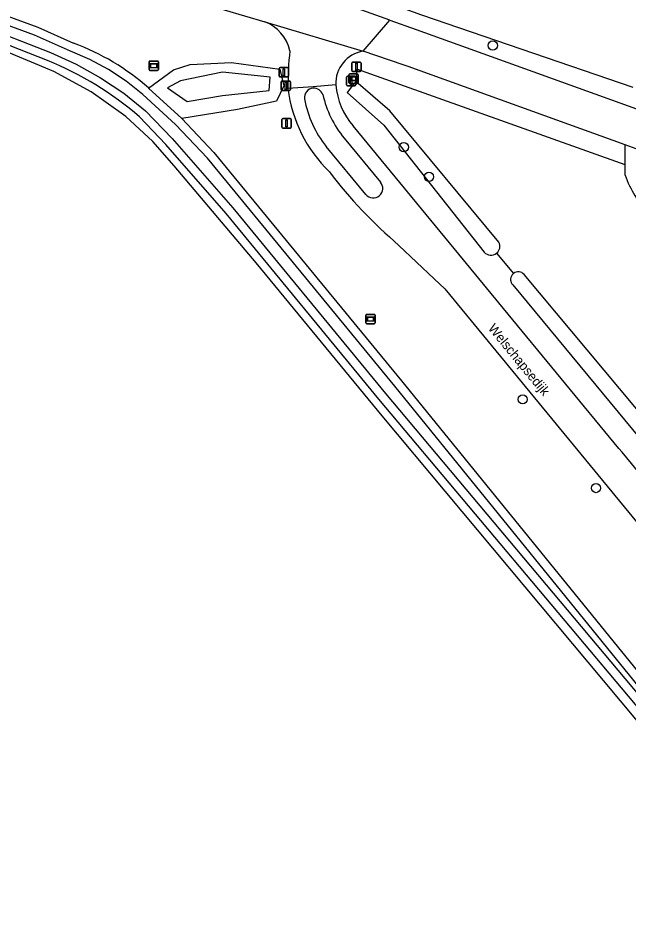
# Model space of a CAD drawing. Extents: x 156061 to 157804, y 383451 to 385640.
# Drawn here: x 156564.9 to 156629.3, y 384979.6 to 385074 of the extents above; entities that cross this region are included whole.
import ezdxf

# ---------------------------------------------------------------- set-up
doc = ezdxf.new("R2010")
doc.units = 0
for name, color, linetype in [('IMGEO_Afsluitpaal', 7, 'Continuous'), ('IMGEO_Berm_groen', 7, 'Continuous'), ('IMGEO_Boom', 7, 'Continuous'), ('IMGEO_Fietspad_gesloten', 7, 'Continuous'), ('IMGEO_Fietspad_open', 7, 'Continuous'), ('IMGEO_Groenvoorziening', 7, 'Continuous'), ('IMGEO_Loofbos', 7, 'Continuous'), ('IMGEO_Openbare_ruimte_label', 7, 'Continuous'), ('IMGEO_Rijbaan_lokaal_gesloten', 7, 'Continuous'), ('IMGEO_Rijbaan_lokaal_open', 7, 'Continuous'), ('IMGEO_Verkeersbordpaal', 7, 'Continuous'), ('IMGEO_Verklikker', 7, 'Continuous'), ('IMGEO_Waterloop', 7, 'Continuous')]:
    doc.layers.add(name, color=color, linetype=linetype)

msp = doc.modelspace()

# ---------------------------------------------------------------- linework, layer by layer
at = {"layer": 'IMGEO_Afsluitpaal'}
for p, q in [((156592.644, 385066.48), (156592.644, 385067.28)), ((156592.644, 385067.28), (156592.644, 385066.48)), ((156592.744, 385067.38), (156593.534, 385067.38)), ((156593.534, 385067.38), (156592.744, 385067.38)), ((156593.634, 385067.28), (156593.634, 385066.48)), ((156593.634, 385066.48), (156593.634, 385067.28)), ((156593.534, 385066.38), (156592.744, 385066.38)), ((156592.744, 385066.38), (156593.534, 385066.38))]:
    msp.add_line(p, q, dxfattribs=at)
msp.add_lwpolyline([(156593.064, 385067.255), (156593.214, 385067.255), (156593.214, 385066.505), (156593.064, 385066.505), (156593.064, 385067.255)], dxfattribs=at)
for centre, start, end in [((156592.744, 385067.28), 90, 180), ((156592.744, 385067.28), 90, 180), ((156593.534, 385067.28), 0, 90), ((156593.534, 385067.28), 360, 90), ((156592.744, 385066.48), 180, 270), ((156592.744, 385066.48), 180, 270), ((156593.534, 385066.48), 270, 0), ((156593.534, 385066.48), 270, 0)]:
    msp.add_arc(centre, 0.1, start, end, dxfattribs=at)
at = {"layer": 'IMGEO_Berm_groen'}
for points in [[(156628.988, 385058.529), (156600.645, 385068.645), (156600.53, 385067.343)], [(156628.988, 385058.529), (156628.997, 385060.649)], [(156615.412, 385049.211), (156617.202, 385047.075)]]:
    msp.add_lwpolyline(points, dxfattribs=at)
at = {"layer": 'IMGEO_Boom'}
for centre in [(156615.004, 385071.134), (156605.602, 385060.399), (156608.268, 385057.279), (156618.158, 385033.777), (156625.908, 385024.415)]:
    msp.add_circle(centre, 0.489, dxfattribs=at)
at = {"layer": 'IMGEO_Fietspad_gesloten'}
for points in [[(156598.43, 385066.983), (156596.028, 385066.78), (156593.377, 385066.578)], [(156952.011, 384636.1), (156951.649, 384636.454), (156945.248, 384644.122), (156913.262, 384682.917), (156857.952, 384750), (156766.231, 384861.244), (156717.241, 384920.698), (156651.898, 385000), (156634.534, 385021.048), (156628.661, 385028.193), (156628.314, 385028.596), (156616.132, 385043.374), (156611.412, 385049.1), (156600.259, 385062.638)], [(156601.608, 385055.389), (156597.416, 385060.46)], [(156599.308, 385061.359), (156603.145, 385056.713)], [(156605.091, 385050.034), (156608.817, 385046.509), (156609.374, 385045.976), (156609.93, 385045.436), (156647.34, 385000), (156714.453, 384918.502), (156763.606, 384858.813), (156853.32, 384750), (156910.525, 384680.616)]]:
    msp.add_lwpolyline(points, dxfattribs=at)
for centre, radius, start, end in [((156607.945, 385068.367), 14.677, 186.9996, 226.02597), ((156596.118, 385065.621), 1.007, 94.46915, 187.32789), ((156596.092, 385065.59), 1.037, 20.93037, 92.86408), ((156606.147, 385067.674), 7.748, 185.11591, 220.54078), ((156606.423, 385067.609), 11.499, 190.60349, 218.44042), ((156607.812, 385068.363), 11.017, 192.60084, 219.47845), ((156637.682, 385088.158), 50.156, 217.24271, 229.47375), ((156602.372, 385056.056), 1.014, 221.10182, 40.38261)]:
    msp.add_arc(centre, radius, start, end, dxfattribs=at)
at = {"layer": 'IMGEO_Fietspad_open'}
for centre, radius, start, end in [((156589.468, 385069.69), 4.199, 12.27269, 69.6849), ((156628.596, 385066.878), 35.221, 173.96373, 180.48847), ((156601.862, 385067.137), 3.436, 99.13504, 182.56298)]:
    msp.add_arc(centre, radius, start, end, dxfattribs=at)
at = {"layer": 'IMGEO_Groenvoorziening'}
for points in [[(156435.058, 385119.831), (156500, 385096.915), (156553.673, 385077.975), (156566.959, 385073.059), (156570.736, 385071.384)], [(156567.978, 385069.561), (156552.813, 385075.489), (156500, 385094.073), (156435.738, 385116.684), (156396.115, 385073.309)], [(156704.185, 384910.355), (156680.539, 384938.812), (156675.709, 384944.624), (156664.3, 384958.479), (156630.109, 385000), (156603.329, 385032.022), (156590.034, 385048.185), (156581.376, 385058.421), (156579.11, 385060.987), (156576.247, 385063.649), (156574.166, 385065.132), (156572.592, 385066.255), (156568.65, 385068.402), (156563.107, 385070.714), (156551.893, 385074.785), (156500, 385093.06), (156436.131, 385115.542), (156397.25, 385072.572), (156397.423, 385071.829)], [(156566.301, 385089.228), (156607.493, 385074.38), (156629.792, 385066.728)], [(156578.657, 385066.646), (156581.272, 385068.56), (156583.033, 385069.112), (156587.408, 385069.329), (156592.511, 385068.62), (156592.952, 385066.882), (156592.158, 385065.258), (156588.056, 385064.392), (156582.153, 385063.43)], [(156582.153, 385063.43), (156578.657, 385066.646)], [(156673.482, 384950.407), (156672.799, 384949.599), (156658.27, 384967.539), (156631.387, 385000), (156602.972, 385033.813), (156586.855, 385053.4), (156580.462, 385060.696), (156577.709, 385063.589)], [(156582.153, 385063.43), (156585.552, 385059.831), (156605.373, 385035.73), (156634.41, 385000), (156674.271, 384951.339), (156673.482, 384950.407)]]:
    msp.add_lwpolyline(points, dxfattribs=at)
for centre, radius, start, end in [((156561.982, 385047.759), 25.195, 48.55963, 69.66829), ((156554.665, 385036.954), 35.22, 49.13426, 67.79013)]:
    msp.add_arc(centre, radius, start, end, dxfattribs=at)
at = {"layer": 'IMGEO_Loofbos'}
msp.add_lwpolyline([(156628.983, 385057.433), (156628.988, 385058.529)], dxfattribs=at)
msp.add_arc((156640.277, 385061.528), 12.014, 199.92856, 222.69113, dxfattribs=at)
at = {"layer": 'IMGEO_Rijbaan_lokaal_gesloten'}
for points in [[(156324.12, 385168.823), (156326.224, 385167.859), (156431.778, 385130.12), (156500, 385105.742), (156557.53, 385085.067), (156567.974, 385081.116), (156578.058, 385077.449), (156590.926, 385073.627)], [(156604.139, 385073.809), (156569.753, 385086.114)], [(156601.317, 385070.529), (156604.139, 385073.809)], [(156590.926, 385073.627), (156601.317, 385070.529)]]:
    msp.add_lwpolyline(points, dxfattribs=at)
at = {"layer": 'IMGEO_Rijbaan_lokaal_open'}
for points in [[(156604.139, 385073.809), (156606.916, 385072.811), (156634.591, 385062.861), (156662.26, 385052.848), (156695.623, 385040.804)], [(156628.997, 385060.649), (156606.086, 385068.91), (156605.548, 385069.093), (156601.317, 385070.529)], [(156632.086, 385059.534), (156628.997, 385060.649)]]:
    msp.add_lwpolyline(points, dxfattribs=at)
at = {"layer": 'IMGEO_Verkeersbordpaal'}
for p, q in [((156600.108, 385068.48), (156600.108, 385069.28)), ((156600.108, 385069.28), (156600.108, 385068.48)), ((156600.208, 385069.38), (156600.998, 385069.38)), ((156600.998, 385069.38), (156600.208, 385069.38)), ((156601.098, 385069.28), (156601.098, 385068.48)), ((156601.098, 385068.48), (156601.098, 385069.28)), ((156592.443, 385067.912), (156592.443, 385068.712)), ((156592.443, 385068.712), (156592.443, 385067.912)), ((156592.543, 385068.812), (156593.333, 385068.812)), ((156593.333, 385068.812), (156592.543, 385068.812)), ((156593.433, 385068.712), (156593.433, 385067.912)), ((156593.433, 385067.912), (156593.433, 385068.712)), ((156600.998, 385068.38), (156600.208, 385068.38)), ((156600.208, 385068.38), (156600.998, 385068.38)), ((156593.333, 385067.812), (156592.543, 385067.812)), ((156592.543, 385067.812), (156593.333, 385067.812)), ((156599.552, 385066.982), (156599.552, 385067.782)), ((156599.552, 385067.782), (156599.552, 385066.982)), ((156599.652, 385067.882), (156600.442, 385067.882)), ((156600.442, 385067.882), (156599.652, 385067.882)), ((156600.542, 385067.782), (156600.542, 385066.982)), ((156600.542, 385066.982), (156600.542, 385067.782)), ((156600.442, 385066.882), (156599.652, 385066.882)), ((156599.652, 385066.882), (156600.442, 385066.882)), ((156592.738, 385062.52), (156592.738, 385063.32)), ((156592.738, 385063.32), (156592.738, 385062.52)), ((156592.838, 385063.42), (156593.628, 385063.42)), ((156593.628, 385063.42), (156592.838, 385063.42)), ((156593.728, 385063.32), (156593.728, 385062.52)), ((156593.728, 385062.52), (156593.728, 385063.32)), ((156593.628, 385062.42), (156592.838, 385062.42)), ((156592.838, 385062.42), (156593.628, 385062.42))]:
    msp.add_line(p, q, dxfattribs=at)
for points in [[(156600.528, 385069.255), (156600.678, 385069.255), (156600.678, 385068.505), (156600.528, 385068.505), (156600.528, 385069.255)], [(156592.863, 385068.687), (156593.013, 385068.687), (156593.013, 385067.937), (156592.863, 385067.937), (156592.863, 385068.687)], [(156599.972, 385067.757), (156600.122, 385067.757), (156600.122, 385067.007), (156599.972, 385067.007), (156599.972, 385067.757)], [(156593.158, 385063.295), (156593.308, 385063.295), (156593.308, 385062.545), (156593.158, 385062.545), (156593.158, 385063.295)]]:
    msp.add_lwpolyline(points, dxfattribs=at)
for centre, start, end in [((156600.208, 385069.28), 90, 180), ((156600.208, 385069.28), 90, 180), ((156600.998, 385069.28), 0, 90), ((156600.998, 385069.28), 360, 90), ((156592.543, 385068.712), 90, 180), ((156592.543, 385068.712), 90, 180), ((156593.333, 385068.712), 0, 90), ((156593.333, 385068.712), 360, 90), ((156600.208, 385068.48), 180, 270), ((156600.208, 385068.48), 180, 270), ((156600.998, 385068.48), 270, 0), ((156600.998, 385068.48), 270, 0), ((156592.543, 385067.912), 180, 270), ((156592.543, 385067.912), 180, 270), ((156593.333, 385067.912), 270, 0), ((156593.333, 385067.912), 270, 0), ((156599.652, 385067.782), 90, 180), ((156599.652, 385067.782), 90, 180), ((156600.442, 385067.782), 0, 90), ((156600.442, 385067.782), 360, 90), ((156599.652, 385066.982), 180, 270), ((156599.652, 385066.982), 180, 270), ((156600.442, 385066.982), 270, 0), ((156600.442, 385066.982), 270, 0), ((156592.838, 385063.32), 90, 180), ((156592.838, 385063.32), 90, 180), ((156593.628, 385063.32), 0, 90), ((156593.628, 385063.32), 360, 90), ((156592.838, 385062.52), 180, 270), ((156592.838, 385062.52), 180, 270), ((156593.628, 385062.52), 270, 0), ((156593.628, 385062.52), 270, 0)]:
    msp.add_arc(centre, 0.1, start, end, dxfattribs=at)
at = {"layer": 'IMGEO_Verklikker'}
for p, q in [((156578.703, 385068.592), (156578.703, 385069.392)), ((156578.703, 385069.392), (156578.703, 385068.592)), ((156578.803, 385069.492), (156579.593, 385069.492)), ((156579.593, 385069.492), (156578.803, 385069.492)), ((156579.693, 385069.392), (156579.693, 385068.592)), ((156579.693, 385068.592), (156579.693, 385069.392)), ((156579.593, 385068.492), (156578.803, 385068.492)), ((156578.803, 385068.492), (156579.593, 385068.492)), ((156599.8, 385067.23), (156599.8, 385068.03)), ((156599.8, 385068.03), (156599.8, 385067.23)), ((156599.9, 385068.13), (156600.69, 385068.13)), ((156600.69, 385068.13), (156599.9, 385068.13)), ((156600.79, 385068.03), (156600.79, 385067.23)), ((156600.79, 385067.23), (156600.79, 385068.03)), ((156600.69, 385067.13), (156599.9, 385067.13)), ((156599.9, 385067.13), (156600.69, 385067.13)), ((156601.594, 385041.848), (156601.594, 385042.648)), ((156601.594, 385042.648), (156601.594, 385041.848)), ((156601.694, 385042.748), (156602.484, 385042.748)), ((156602.484, 385042.748), (156601.694, 385042.748)), ((156602.584, 385042.648), (156602.584, 385041.848)), ((156602.584, 385041.848), (156602.584, 385042.648)), ((156602.484, 385041.748), (156601.694, 385041.748)), ((156601.694, 385041.748), (156602.484, 385041.748))]:
    msp.add_line(p, q, dxfattribs=at)
for points in [[(156578.804, 385069.224), (156579.592, 385069.224), (156579.592, 385068.76), (156578.804, 385068.76), (156578.804, 385069.224)], [(156578.869, 385069.159), (156578.869, 385068.825), (156579.527, 385068.825), (156579.527, 385069.159), (156578.869, 385069.159)], [(156599.901, 385067.862), (156600.689, 385067.862), (156600.689, 385067.398), (156599.901, 385067.398), (156599.901, 385067.862)], [(156599.966, 385067.797), (156599.966, 385067.463), (156600.624, 385067.463), (156600.624, 385067.797), (156599.966, 385067.797)], [(156601.695, 385042.48), (156602.483, 385042.48), (156602.483, 385042.016), (156601.695, 385042.016), (156601.695, 385042.48)], [(156601.76, 385042.415), (156601.76, 385042.081), (156602.418, 385042.081), (156602.418, 385042.415), (156601.76, 385042.415)]]:
    msp.add_lwpolyline(points, dxfattribs=at)
for centre, start, end in [((156578.803, 385069.392), 90, 180), ((156578.803, 385069.392), 90, 180), ((156579.593, 385069.392), 0, 90), ((156579.593, 385069.392), 360, 90), ((156578.803, 385068.592), 180, 270), ((156578.803, 385068.592), 180, 270), ((156579.593, 385068.592), 270, 0), ((156579.593, 385068.592), 270, 0), ((156599.9, 385068.03), 90, 180), ((156599.9, 385068.03), 90, 180), ((156600.69, 385068.03), 0, 90), ((156600.69, 385068.03), 360, 90), ((156599.9, 385067.23), 180, 270), ((156599.9, 385067.23), 180, 270), ((156600.69, 385067.23), 270, 0), ((156600.69, 385067.23), 270, 0), ((156601.694, 385042.648), 90, 180), ((156601.694, 385042.648), 90, 180), ((156602.484, 385042.648), 0, 90), ((156602.484, 385042.648), 360, 90), ((156601.694, 385041.848), 180, 270), ((156601.694, 385041.848), 180, 270), ((156602.484, 385041.848), 270, 0), ((156602.484, 385041.848), 270, 0)]:
    msp.add_arc(centre, 0.1, start, end, dxfattribs=at)
at = {"layer": 'IMGEO_Waterloop'}
for points in [[(156553.128, 385076.338), (156568.314, 385070.402), (156571, 385069.176), (156573.577, 385067.734), (156576.027, 385066.087), (156578.335, 385064.245), (156581.131, 385061.307), (156587.545, 385053.986), (156603.668, 385034.392), (156632.082, 385000.58), (156658.971, 384968.113), (156672.814, 384951.02), (156673.092, 384951.349), (156633.708, 384999.427), (156604.672, 385035.157), (156584.872, 385059.232), (156581.516, 385062.785), (156578.051, 385065.973), (156576.304, 385067.377), (156574.434, 385068.613), (156572.459, 385069.672), (156570.395, 385070.544), (156566.618, 385072.219), (156553.365, 385077.123)], [(156582.746, 385065.206), (156586.48, 385065.856), (156591.391, 385066.373), (156591.48, 385067.774), (156586.463, 385068.332), (156582.016, 385067.419), (156580.658, 385066.659), (156582.746, 385065.206)], [(156600.53, 385067.343), (156600.103, 385066.784), (156599.637, 385066.174), (156603.501, 385062.717), (156614.108, 385049.309)], [(156615.649, 385050.37), (156604.118, 385064.231), (156600.53, 385067.343)], [(156617.202, 385047.075), (156617.04, 385046.911)], [(156633.422, 385028.896), (156618.313, 385046.971)], [(156617.114, 385045.869), (156632.123, 385027.749)]]:
    msp.add_lwpolyline(points, dxfattribs=at)
for centre, radius, start, end in [((156614.811, 385049.938), 0.943, 309.57916, 27.30705), ((156614.811, 385049.937), 0.942, 221.7637, 309.64052), ((156617.7, 385046.413), 0.829, 42.32919, 126.97514), ((156617.701, 385046.434), 0.815, 144.19006, 223.93428)]:
    msp.add_arc(centre, radius, start, end, dxfattribs=at)

# ---------------------------------------------------------------- texts
at = {"layer": 'IMGEO_Openbare_ruimte_label'}
msp.add_text('Welschapsedijk', height=1, rotation=309.35796, dxfattribs=at).set_placement((156614.447, 385041.245))

doc.saveas('drawing.dxf')
